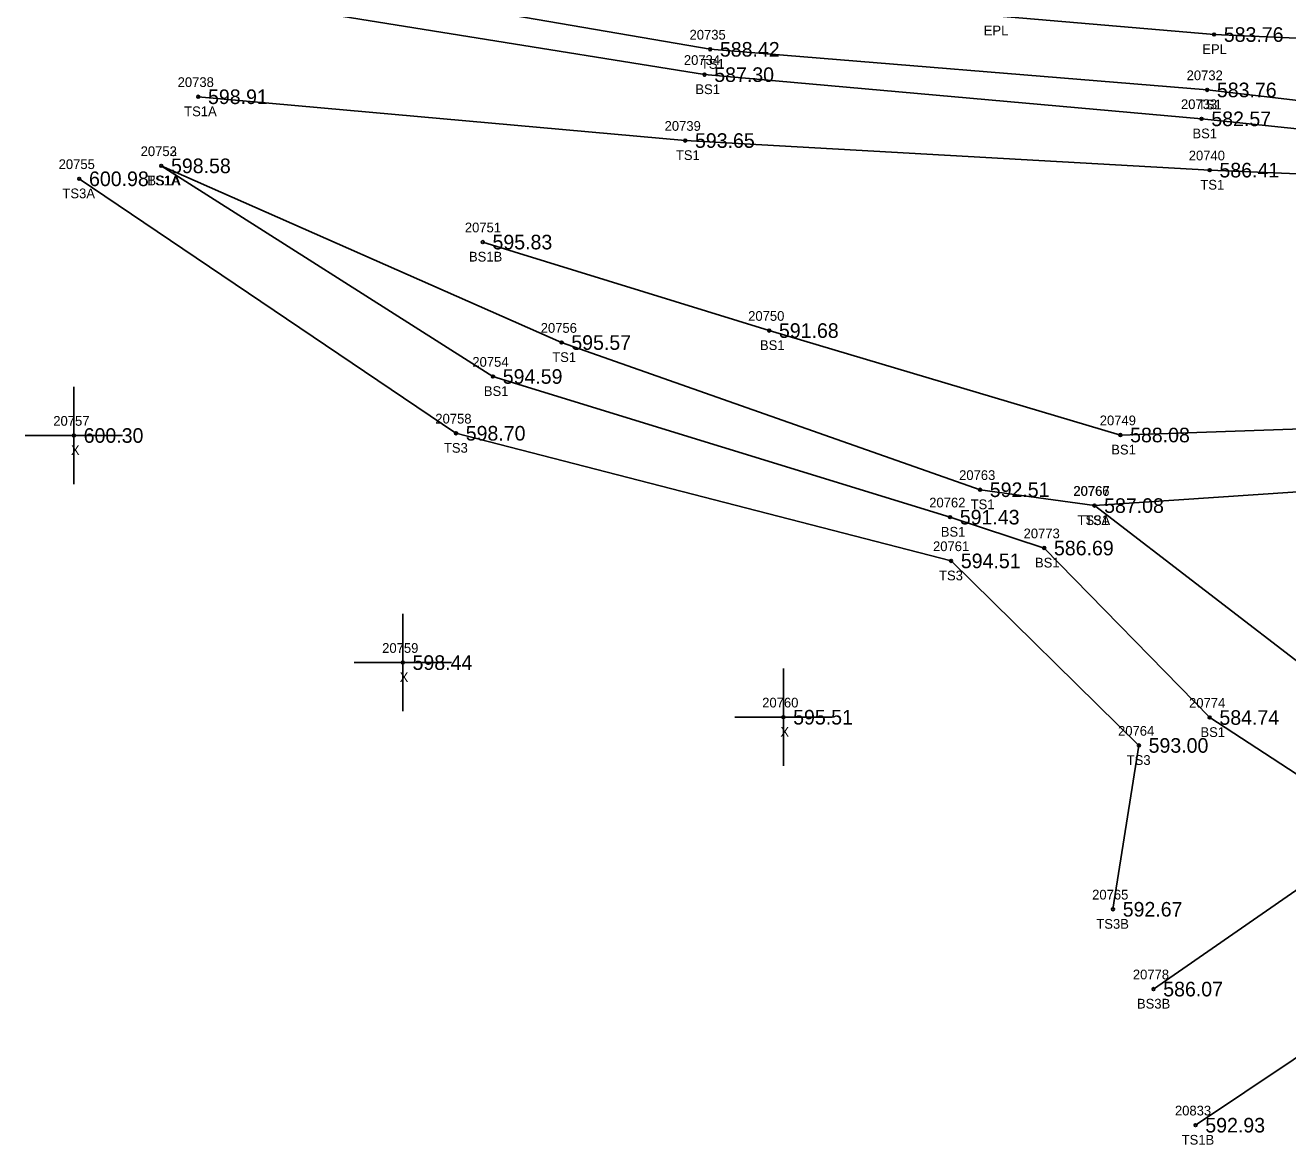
# Model space of a CAD drawing. Extents: x 1540443 to 1541844, y 887157 to 888162.
# Drawn here: x 1540443.3 to 1540572.9, y 887431.6 to 887546.6 of the extents above; entities that cross this region are included whole.
import ezdxf

# ---------------------------------------------------------------- set-up
doc = ezdxf.new("R2010")
doc.units = 0
for name, color, linetype in [('RD_DTM_BkLn2', 7, 'Continuous'), ('RD_DTM_BkLn_txCode', 7, 'Continuous'), ('RD_EX_Misc', 7, 'Continuous'), ('RD_EX_Misc_txCode', 7, 'Continuous'), ('RD_EX_Road', 7, 'Continuous'), ('RD_EX_Road_txCode', 7, 'Continuous'), ('RD_EX_TX_Misc_ELEV', 7, 'Continuous'), ('RD_EX_TX_Road_ELEV', 7, 'Continuous'), ('RD_SMD_Locator', 7, 'Continuous')]:
    doc.layers.add(name, color=color, linetype=linetype)

msp = doc.modelspace()

# ---------------------------------------------------------------- linework, layer by layer
at = {"layer": 'RD_DTM_BkLn2'}
for p, q in [((1540553.06, 887497.25), (1540578.57, 887477.63)), ((1540582.63, 887463.9), (1540559.13, 887447.58))]:
    msp.add_line(p, q, dxfattribs=at)
for points in [[(1540960.58, 887575.27), (1540958.57, 887598.03), (1540949.34, 887601.53), (1540912.42, 887588.35), (1540865.58, 887574.46), (1540822.62, 887563.37), (1540767.41, 887547.91), (1540718.66, 887535.26), (1540668.13, 887523.76), (1540649.26, 887523.14), (1540607.24, 887534.95), (1540564.64, 887539.95), (1540513.61, 887544.12), (1540463.72, 887552.73)], [(1540960.58, 887575.27), (1540955.45, 887594.2), (1540950.03, 887596.51), (1540913.42, 887584.06), (1540866.75, 887567.94), (1540825.46, 887557.08), (1540769.44, 887540.76), (1540737.8, 887532.98), (1540709.87, 887528.84), (1540668.36, 887521.72), (1540649.18, 887520.9), (1540606.9, 887532.51), (1540564.07, 887536.98), (1540513.03, 887541.52), (1540462.71, 887549.66)], [(1540461.05, 887539.25), (1540511.05, 887534.75), (1540564.9, 887531.71), (1540604.16, 887530.05), (1540635.87, 887521.25), (1540658.77, 887517.54), (1540669.35, 887519.1)], [(1540457.25, 887532.15), (1540491.31, 887510.51), (1540538.24, 887496.06), (1540547.91, 887492.89), (1540564.9, 887475.48), (1540582.63, 887463.9), (1540605.15, 887456.78), (1540619.78, 887467.58), (1540627.99, 887476.17), (1540639.08, 887475.86), (1540647.69, 887483.2), (1540666.45, 887494.92), (1540676.29, 887496.62), (1540688.39, 887506.9), (1540704.43, 887509.26), (1540713.49, 887518.97), (1540737.81, 887533.15)], [(1540457.25, 887532.15), (1540498.35, 887514), (1540541.32, 887498.88), (1540553.06, 887497.25), (1540586.16, 887499.5)], [(1540448.83, 887530.82), (1540487.51, 887504.68), (1540538.35, 887491.57), (1540557.63, 887472.61), (1540554.97, 887455.78)], [(1540669.35, 887519.1), (1540658.72, 887515.92), (1540619.9, 887509.56), (1540591.08, 887505.72), (1540555.73, 887504.5), (1540519.67, 887515.23), (1540490.26, 887524.32)], [(1540644.3, 887459.39), (1540630.81, 887455.74), (1540618.7, 887444.2), (1540601.41, 887439.89), (1540578.52, 887443.69), (1540563.45, 887433.6)]]:
    msp.add_lwpolyline(points, dxfattribs=at)
at = {"layer": 'RD_EX_Misc'}
for p, q in [((1540448.28, 887499.45), (1540448.28, 887509.45)), ((1540443.28, 887504.45), (1540453.28, 887504.45)), ((1540482.05, 887476.12), (1540482.05, 887486.12)), ((1540477.05, 887481.12), (1540487.05, 887481.12)), ((1540521.13, 887470.51), (1540521.13, 887480.51)), ((1540516.13, 887475.51), (1540526.13, 887475.51))]:
    msp.add_line(p, q, dxfattribs=at)
at = {"layer": 'RD_EX_Road'}
msp.add_lwpolyline([(1541128.99, 887664.81), (1541102.04, 887656.79), (1541055.37, 887642.78), (1541004.6, 887628.06), (1540958.93, 887614.62), (1540910.77, 887599.96), (1540863.12, 887586.35), (1540837, 887578.35), (1540814.37, 887572.63), (1540785.6, 887565.57), (1540765.56, 887561), (1540743.15, 887555.32), (1540714.84, 887552.19), (1540688.66, 887548.15), (1540665.15, 887545.04), (1540640.91, 887544.2), (1540614.99, 887544.1), (1540590.77, 887544.52), (1540565.35, 887545.64), (1540542.9, 887547.56), (1540513.68, 887550.75), (1540490.5, 887554.02), (1540464.65, 887559.04)], dxfattribs=at)
at = {"layer": 'RD_SMD_Locator'}
for centre in [(1540565.35, 887545.64), (1540513.61, 887544.12), (1540513.03, 887541.52), (1540461.05, 887539.25), (1540564.64, 887539.95), (1540564.07, 887536.98), (1540511.05, 887534.75), (1540457.25, 887532.15), (1540457.25, 887532.15), (1540564.9, 887531.71), (1540448.83, 887530.82), (1540490.26, 887524.32), (1540519.67, 887515.23), (1540498.35, 887514), (1540491.31, 887510.51), (1540448.28, 887504.45), (1540487.51, 887504.68), (1540555.73, 887504.5), (1540541.32, 887498.88), (1540553.06, 887497.25), (1540553.06, 887497.25), (1540538.24, 887496.06), (1540547.91, 887492.89), (1540538.35, 887491.57), (1540482.05, 887481.12), (1540521.13, 887475.51), (1540564.9, 887475.48), (1540557.63, 887472.61), (1540554.97, 887455.78), (1540559.13, 887447.58), (1540563.45, 887433.6)]:
    msp.add_circle(centre, 0.15, dxfattribs=at)

# ---------------------------------------------------------------- texts
at = {"layer": 'RD_DTM_BkLn_txCode'}
for s, p in [('20735', (1540511.49, 887545.12)), ('20734', (1540510.91, 887542.52)), ('TS1', (1540512.65, 887542.12)), ('20732', (1540562.53, 887540.95)), ('20738', (1540458.93, 887540.25)), ('BS1', (1540512.09, 887539.52)), ('TS1A', (1540459.6, 887537.25)), ('20733', (1540561.95, 887537.98)), ('TS1', (1540563.68, 887537.95)), ('20739', (1540508.93, 887535.75)), ('BS1', (1540563.13, 887534.98)), ('20752', (1540455.13, 887533.15)), ('20753', (1540455.13, 887533.15)), ('20755', (1540446.71, 887531.82)), ('TS1', (1540510.09, 887532.75)), ('20740', (1540562.75, 887532.71)), ('TS1A', (1540455.8, 887530.15)), ('BS1A', (1540455.82, 887530.15)), ('TS1', (1540563.94, 887529.71)), ('TS3A', (1540447.1, 887528.82)), ('20751', (1540488.42, 887525.32)), ('BS1B', (1540488.84, 887522.32)), ('20756', (1540496.21, 887515)), ('20750', (1540517.51, 887516.23)), ('BS1', (1540518.72, 887513.23)), ('20754', (1540489.19, 887511.51)), ('TS1', (1540497.39, 887512)), ('BS1', (1540490.37, 887508.51)), ('20758', (1540485.39, 887505.68)), ('20749', (1540553.61, 887505.5)), ('TS3', (1540486.27, 887502.68)), ('BS1', (1540554.79, 887502.5)), ('20763', (1540539.17, 887499.88)), ('20766', (1540550.89, 887498.25)), ('20767', (1540550.92, 887498.25)), ('20762', (1540536.1, 887497.06)), ('TS1', (1540540.35, 887496.88)), ('TS3A', (1540551.33, 887495.25)), ('TS1', (1540552.1, 887495.25)), ('BS1', (1540537.29, 887494.06)), ('20773', (1540545.79, 887493.89)), ('20761', (1540536.49, 887492.57)), ('BS1', (1540546.96, 887490.89)), ('TS3', (1540537.11, 887489.57)), ('20774', (1540562.78, 887476.48)), ('20764', (1540555.49, 887473.61)), ('BS1', (1540563.95, 887473.48)), ('TS3', (1540556.38, 887470.61)), ('20765', (1540552.83, 887456.78)), ('TS3B', (1540553.26, 887453.78)), ('20778', (1540557.01, 887448.58)), ('BS3B', (1540557.43, 887445.58)), ('20833', (1540561.33, 887434.6)), ('TS1B', (1540562.02, 887431.6))]:
    msp.add_text(s, height=1, dxfattribs=at).set_placement(p)
at = {"layer": 'RD_EX_Misc_txCode'}
for s, p in [('20757', (1540446.16, 887505.45)), ('X', (1540447.97, 887502.45)), ('20759', (1540479.93, 887482.12)), ('X', (1540481.73, 887479.12)), ('20760', (1540518.95, 887476.51)), ('X', (1540520.82, 887473.51))]:
    msp.add_text(s, height=1, dxfattribs=at).set_placement(p)
at = {"layer": 'RD_EX_Road_txCode'}
for p in [(1540541.7, 887545.56), (1540564.14, 887543.64)]:
    msp.add_text('EPL', height=1, dxfattribs=at).set_placement(p)
at = {"layer": 'RD_EX_TX_Misc_ELEV'}
for s, p in [('588.42', (1540514.61, 887543.37)), ('587.30', (1540514.03, 887540.77)), ('583.76', (1540565.64, 887539.2)), ('598.91', (1540462.05, 887538.5)), ('582.57', (1540565.07, 887536.23)), ('593.65', (1540512.05, 887534)), ('598.58', (1540458.25, 887531.4)), ('598.58', (1540458.25, 887531.4)), ('600.98', (1540449.83, 887530.07)), ('586.41', (1540565.9, 887530.96)), ('595.83', (1540491.26, 887523.57)), ('591.68', (1540520.67, 887514.48)), ('595.57', (1540499.35, 887513.25)), ('594.59', (1540492.31, 887509.76)), ('600.30', (1540449.28, 887503.7)), ('598.70', (1540488.51, 887503.93)), ('588.08', (1540556.73, 887503.75)), ('592.51', (1540542.32, 887498.13)), ('587.08', (1540554.06, 887496.5)), ('587.08', (1540554.06, 887496.5)), ('591.43', (1540539.24, 887495.31)), ('586.69', (1540548.91, 887492.14)), ('594.51', (1540539.35, 887490.82)), ('598.44', (1540483.05, 887480.37)), ('595.51', (1540522.13, 887474.76)), ('584.74', (1540565.9, 887474.73)), ('593.00', (1540558.63, 887471.86)), ('592.67', (1540555.97, 887455.03)), ('586.07', (1540560.13, 887446.83)), ('592.93', (1540564.45, 887432.85))]:
    msp.add_text(s, height=1.5, dxfattribs=at).set_placement(p)
at = {"layer": 'RD_EX_TX_Road_ELEV'}
msp.add_text('583.76', height=1.5, dxfattribs=at).set_placement((1540566.35, 887544.89))

doc.saveas('drawing.dxf')
